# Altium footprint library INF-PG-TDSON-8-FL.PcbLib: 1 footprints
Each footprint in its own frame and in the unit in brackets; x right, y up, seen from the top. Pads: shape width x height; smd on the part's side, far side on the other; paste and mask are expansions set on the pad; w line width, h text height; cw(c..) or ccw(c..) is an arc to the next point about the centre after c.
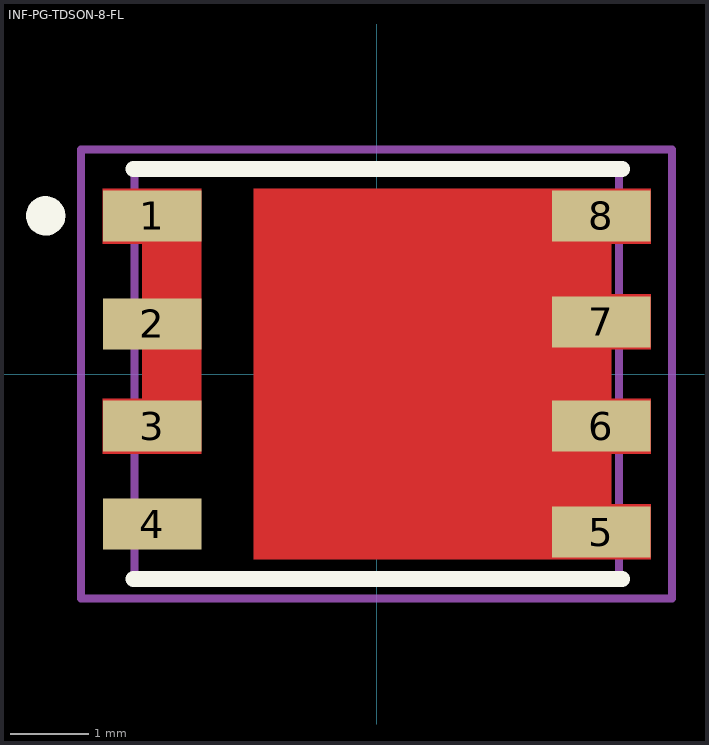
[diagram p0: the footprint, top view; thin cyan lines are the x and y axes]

## INF-PG-TDSON-8-FL [mm] "SON,1.27mm pitch;8 pin,6.15mm W X 5.15mm L X 1.10mm H body"
height 1.1
pads (8):
  rect 1.25x0.65 smd paste+0 mask+0: 1(-2.85,2.007) 2(-2.85,0.635) 3(-2.85,-0.66) 4(-2.85,-1.905) 5(2.85,-2.007) 6(2.85,-0.66) 7(2.85,0.66) 8(2.85,2.007)
Top Layer:
  region: 2.975,-0.315 2.975,-1.015 3.475,-1.015 3.475,-0.315
  region: 2.975,1.015 2.975,0.315 3.475,0.315 3.475,1.015
  region: 2.975,-1.65 2.975,-2.35 3.475,-2.35 3.475,-1.65
  region: 2.975,2.35 -1.559,2.35 -1.559,-2.35 2.975,-2.35
  region: 2.975,2.35 2.975,1.65 3.475,1.65 3.475,2.35
  region: -2.975,1.65 -2.975,2.35 -3.475,2.35 -3.475,1.65
  region: -2.975,-1.015 -2.975,-0.315 -3.475,-0.315 -3.475,-1.015
  region: -2.975,-1.015 -2.225,-1.015 -2.225,2.35 -2.975,2.35
Top Overlay:
  circle w0.25: c-4.2,2.007 r0.125
  lines w0.2: -3.084,-2.6 3.116,-2.6 ; -3.084,2.6 3.116,2.6
Mechanical 3:
  text ".DESIGNATOR" at 0,0 h1.2
Mechanical 13:
  lines w0.1: -3.075,-2.575 -3.075,2.575 3.075,2.575 3.075,-2.575 -3.075,-2.575
Mechanical 15:
  lines w0.1: -0.5,0 0.5,0 ; 0,-0.5 0,0.5 ; -3.75,-2.85 -3.75,2.85 3.75,2.85 3.75,-2.85 -3.75,-2.85
3D body: height 1.01, standoff 0, extent -3.075,-2.695 3.075,2.695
